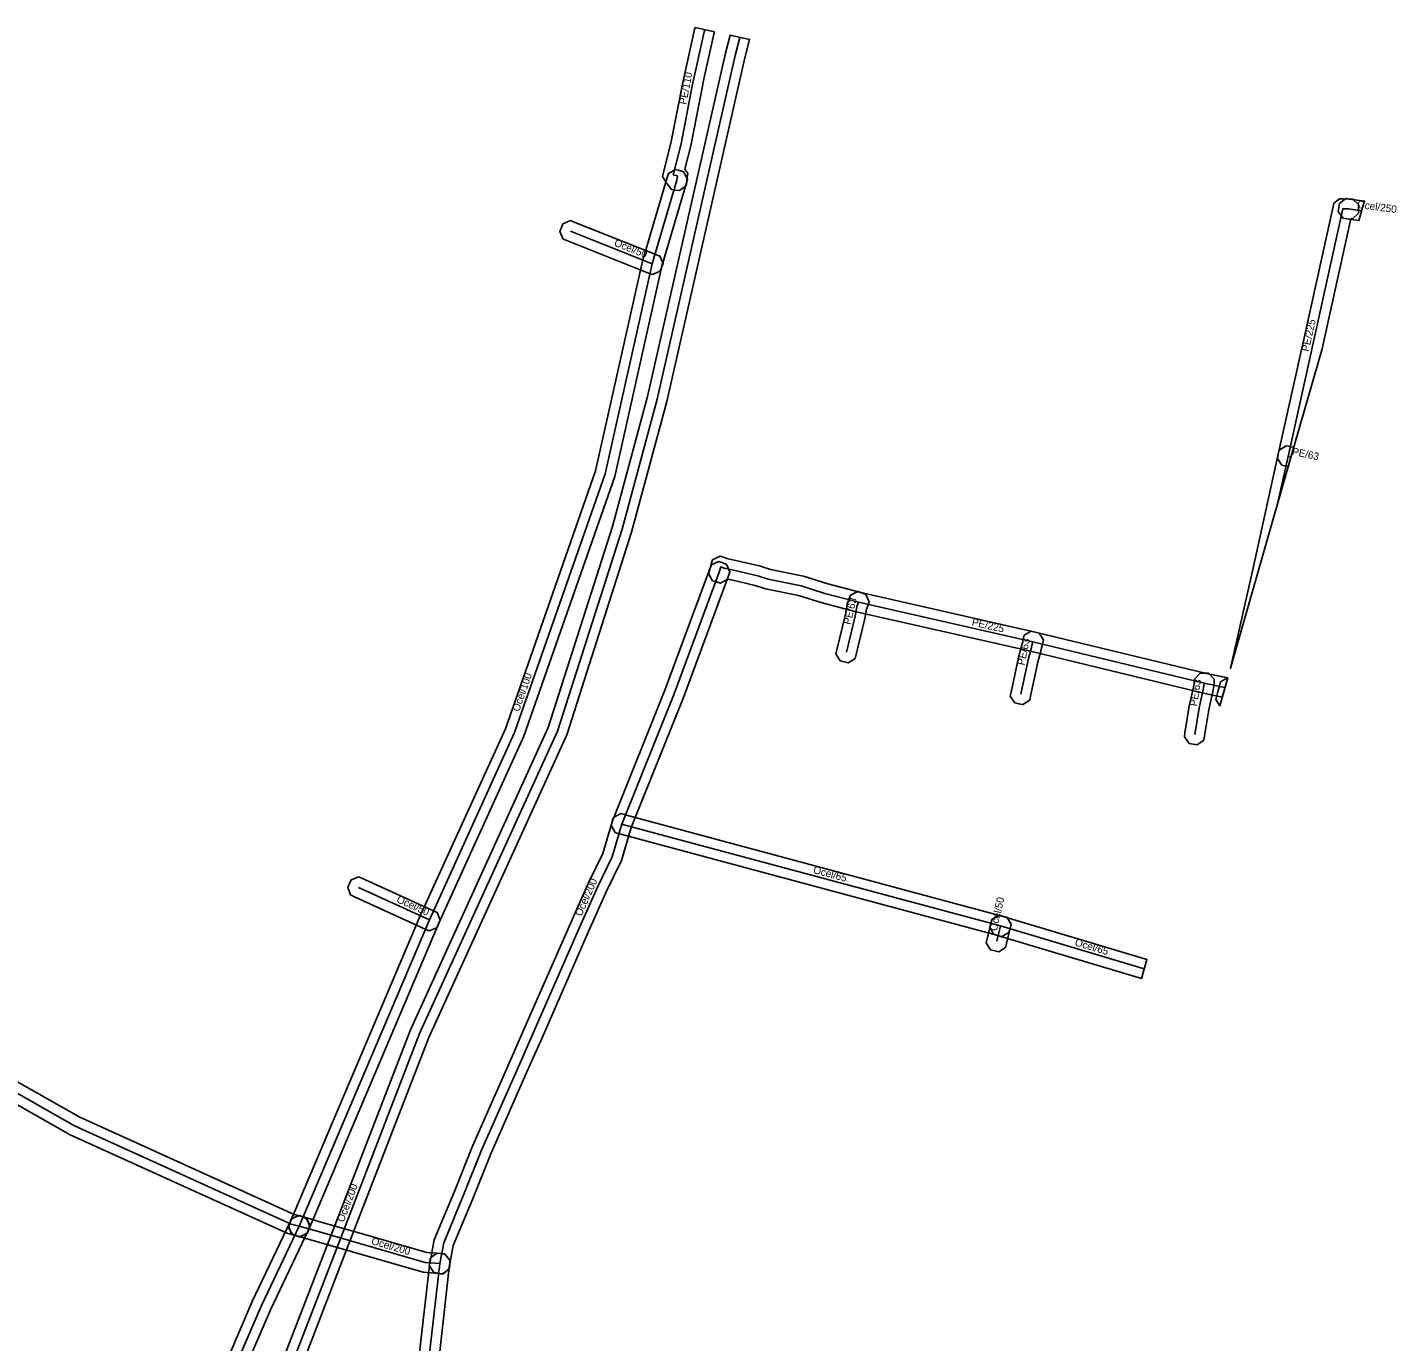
# Model space of a CAD drawing. Extents: x -702919 to -702657, y -1012371 to -1012107.
# Drawn here: x -702794.8 to -702657.1, y -1012238.8 to -1012106.7 of the extents above; entities that cross this region are included whole.
import ezdxf

# ---------------------------------------------------------------- set-up
doc = ezdxf.new("R2010")
doc.units = 0
for name, color, linetype in [('1', 7, 'Continuous'), ('14', 7, 'Continuous'), ('20', 7, 'Continuous'), ('24', 7, 'Continuous'), ('30', 7, 'Continuous')]:
    doc.layers.add(name, color=color, linetype=linetype)

msp = doc.modelspace()

# ---------------------------------------------------------------- linework, layer by layer
at = {"layer": '1'}
for points in [[(-702771.48, -1012246.91), (-702764.83, -1012229.68), (-702756.24, -1012207.49), (-702742.38, -1012177.11), (-702735.92, -1012156.89), (-702732.39, -1012143.83), (-702724.56, -1012109.28), (-702724.09, -1012107.49), (-702722.13, -1012107.92), (-702722.61, -1012109.75), (-702730.45, -1012144.31), (-702734, -1012157.46), (-702740.51, -1012177.83), (-702754.4, -1012208.27), (-702762.96, -1012230.4), (-702769.42, -1012247.1)], [(-702803.11, -1012208.58), (-702789.55, -1012216.25), (-702767.92, -1012226.08), (-702767.17, -1012226.27), (-702766.77, -1012226.37), (-702766.35, -1012227.09), (-702766.45, -1012227.49), (-702766.55, -1012227.89), (-702767.27, -1012228.31), (-702767.67, -1012228.21), (-702768.58, -1012227.98), (-702790.46, -1012218.04), (-702804.11, -1012210.31)], [(-702774.49, -1012240.3), (-702772.15, -1012234.82), (-702768.32, -1012226.81), (-702768.14, -1012226.44), (-702767.36, -1012226.16), (-702766.99, -1012226.34), (-702766.61, -1012226.52), (-702766.34, -1012227.3), (-702766.52, -1012227.67), (-702770.32, -1012235.65), (-702772.41, -1012240.53)]]:
    msp.add_lwpolyline(points, dxfattribs=at)
for points in [[(-702727.62, -1012106.7), (-702725.67, -1012107.14), (-702725.73, -1012107.38), (-702726.83, -1012112.35), (-702726.85, -1012112.45), (-702728.05, -1012118.63), (-702728.64, -1012120.96), (-702728.35, -1012121.39), (-702728.4, -1012121.78), (-702728.46, -1012122.21), (-702728.52, -1012122.62), (-702729.18, -1012123.12), (-702729.59, -1012123.06), (-702730, -1012123), (-702730.44, -1012122.42), (-702730.45, -1012122.42), (-702730.67, -1012122.06), (-702730.89, -1012121.7), (-702730.79, -1012121.3), (-702730.01, -1012118.19), (-702728.81, -1012112.07), (-702728.79, -1012111.95), (-702727.67, -1012106.92)], [(-702768.5, -1012227.23), (-702768.34, -1012226.85), (-702755.25, -1012196.04), (-702746.69, -1012177.22), (-702737.63, -1012151.3), (-702732.89, -1012130.22), (-702730.41, -1012121.79), (-702730.29, -1012121.39), (-702729.57, -1012120.99), (-702729.17, -1012121.11), (-702728.77, -1012121.23), (-702728.37, -1012121.95), (-702728.49, -1012122.35), (-702730.95, -1012130.72), (-702735.7, -1012151.85), (-702744.83, -1012177.96), (-702753.42, -1012196.85), (-702766.5, -1012227.63), (-702766.66, -1012228.01), (-702767.43, -1012228.32), (-702767.81, -1012228.16), (-702768.19, -1012228)], [(-702667.73, -1012150.04), (-702673.78, -1012171.14), (-702671.52, -1012161.2), (-702668.97, -1012149.62), (-702666.31, -1012137.63), (-702663.47, -1012124.73), (-702663.39, -1012124.39), (-702662.83, -1012123.94), (-702662.47, -1012123.95), (-702661.88, -1012123.96), (-702661.47, -1012123.97), (-702660.89, -1012124.56), (-702660.9, -1012124.98), (-702660.91, -1012125.39), (-702661.5, -1012125.97), (-702661.69, -1012125.96), (-702664.35, -1012138.07), (-702664.57, -1012139.04)], [(-702660.33, -1012124.26), (-702660.86, -1012126.11), (-702662.04, -1012125.95), (-702662.45, -1012125.9), (-702662.95, -1012125.23), (-702662.89, -1012124.83), (-702662.83, -1012124.42), (-702662.18, -1012123.91), (-702661.77, -1012123.97), (-702660.3, -1012124.17), (-702660.32, -1012124.23)], [(-702731.9, -1012131.55), (-702732.29, -1012131.4), (-702740.5, -1012128.14), (-702740.88, -1012127.99), (-702741.21, -1012127.23), (-702741.06, -1012126.84), (-702740.91, -1012126.46), (-702740.15, -1012126.13), (-702739.76, -1012126.28), (-702731.55, -1012129.54), (-702731.16, -1012129.7), (-702730.83, -1012130.46), (-702730.99, -1012130.84), (-702731.14, -1012131.23)], [(-702667.73, -1012150.04), (-702667.96, -1012150.87), (-702668.2, -1012150.82), (-702668.6, -1012150.73), (-702669.06, -1012150.04), (-702668.97, -1012149.63), (-702668.88, -1012149.22), (-702668.19, -1012148.78), (-702667.78, -1012148.86), (-702667.5, -1012148.92), (-702667.41, -1012148.94)], [(-702674.06, -1012172.11), (-702674.62, -1012174.04), (-702676.63, -1012173.62), (-702693.88, -1012169.44), (-702711.43, -1012165.48), (-702714.84, -1012164.57), (-702717.21, -1012163.83), (-702720.52, -1012163.14), (-702721.57, -1012162.81), (-702723.97, -1012162.26), (-702724.37, -1012162.18), (-702725.06, -1012162.57), (-702725.46, -1012162.45), (-702725.86, -1012162.34), (-702726.27, -1012161.62), (-702726.15, -1012161.22), (-702726, -1012160.68), (-702725.88, -1012160.25), (-702725.48, -1012160.05), (-702725.08, -1012159.86), (-702724.67, -1012160.02), (-702724.41, -1012160.12), (-702724.17, -1012160.17), (-702723.53, -1012160.31), (-702721.05, -1012160.87), (-702720.02, -1012161.2), (-702716.71, -1012161.89), (-702714.28, -1012162.65), (-702710.95, -1012163.54), (-702693.42, -1012167.5), (-702676.19, -1012171.66)], [(-702754.35, -1012231.21), (-702754.27, -1012230.8), (-702753.85, -1012228.61), (-702751.85, -1012223.81), (-702750.01, -1012219.2), (-702746.32, -1012210.86), (-702744.83, -1012207.48), (-702740.29, -1012197.1), (-702738.33, -1012192.73), (-702736.9, -1012189.76), (-702735.93, -1012186.49), (-702730.65, -1012173.35), (-702726.13, -1012161.14), (-702725.98, -1012160.75), (-702725.23, -1012160.41), (-702724.84, -1012160.55), (-702724.45, -1012160.7), (-702724.11, -1012161.45), (-702724.25, -1012161.84), (-702728.79, -1012174.07), (-702734.04, -1012187.15), (-702735.02, -1012190.48), (-702736.51, -1012193.57), (-702738.46, -1012197.91), (-702743, -1012208.29), (-702744.49, -1012211.67), (-702748.17, -1012219.98), (-702750, -1012224.56), (-702751.93, -1012229.19), (-702752.31, -1012231.18), (-702752.39, -1012231.59), (-702753.07, -1012232.05), (-702753.48, -1012231.97), (-702753.89, -1012231.89)], [(-702710.25, -1012164.85), (-702710.37, -1012165.19), (-702710.54, -1012166.13), (-702711.43, -1012169.76), (-702711.53, -1012170.16), (-702712.23, -1012170.59), (-702712.64, -1012170.49), (-702713.04, -1012170.39), (-702713.47, -1012169.69), (-702713.37, -1012169.28), (-702712.5, -1012165.71), (-702712.33, -1012164.78), (-702712.31, -1012164.67), (-702712.13, -1012164.17), (-702711.99, -1012163.78), (-702711.24, -1012163.43), (-702710.85, -1012163.57), (-702710.46, -1012163.71), (-702710.11, -1012164.46)], [(-702692.58, -1012168.3), (-702692.68, -1012168.71), (-702692.77, -1012169.09), (-702692.86, -1012169.44), (-702693.16, -1012170.52), (-702693.88, -1012173.95), (-702693.97, -1012174.35), (-702694.66, -1012174.8), (-702695.07, -1012174.72), (-702695.47, -1012174.63), (-702695.92, -1012173.94), (-702695.84, -1012173.53), (-702695.1, -1012170.06), (-702694.8, -1012168.92), (-702694.71, -1012168.59), (-702694.62, -1012168.23), (-702694.52, -1012167.83), (-702693.82, -1012167.4), (-702693.41, -1012167.5), (-702693.01, -1012167.6)], [(-702677.51, -1012173.06), (-702677.41, -1012172.59), (-702677.41, -1012172.23), (-702676.82, -1012171.64), (-702676.41, -1012171.64), (-702676, -1012171.64), (-702675.41, -1012172.23), (-702675.41, -1012172.64), (-702675.41, -1012172.81), (-702675.56, -1012173.48), (-702675.96, -1012175.32), (-702676.38, -1012177.95), (-702676.45, -1012178.36), (-702677.12, -1012178.84), (-702677.53, -1012178.78), (-702677.94, -1012178.71), (-702678.42, -1012178.04), (-702678.36, -1012177.63), (-702677.92, -1012174.94)], [(-702674.09, -1012172.09), (-702674.06, -1012172.1), (-702674.86, -1012174.91), (-702675.02, -1012174.66), (-702675.24, -1012174.3), (-702675.14, -1012173.89), (-702675.07, -1012173.6), (-702674.9, -1012172.92), (-702674.8, -1012172.52)], [(-702696.77, -1012198.12), (-702697.17, -1012198.02), (-702735.07, -1012187.84), (-702735.27, -1012187.78), (-702735.67, -1012187.66), (-702736.06, -1012186.93), (-702735.94, -1012186.53), (-702735.83, -1012186.14), (-702735.1, -1012185.74), (-702734.7, -1012185.86), (-702734.52, -1012185.92), (-702696.65, -1012196.09), (-702696.25, -1012196.19), (-702695.84, -1012196.91), (-702695.95, -1012197.31), (-702696.06, -1012197.71)], [(-702761.43, -1012192.12), (-702761.05, -1012192.29), (-702753.92, -1012195.54), (-702753.55, -1012195.71), (-702753.26, -1012196.48), (-702753.43, -1012196.86), (-702753.6, -1012197.24), (-702754.37, -1012197.53), (-702754.75, -1012197.36), (-702761.88, -1012194.11), (-702762.26, -1012193.94), (-702762.55, -1012193.17), (-702762.38, -1012192.79), (-702762.2, -1012192.41)], [(-702695.84, -1012196.87), (-702695.94, -1012197.28), (-702696.29, -1012198.81), (-702696.39, -1012199.21), (-702697.09, -1012199.65), (-702697.49, -1012199.56), (-702697.9, -1012199.47), (-702698.34, -1012198.76), (-702698.24, -1012198.36), (-702697.89, -1012196.83), (-702697.79, -1012196.42), (-702697.09, -1012195.98), (-702696.69, -1012196.08), (-702696.28, -1012196.17)], [(-702696.63, -1012196.09), (-702682.19, -1012200.42), (-702682.74, -1012202.34), (-702697.2, -1012198.01), (-702697.6, -1012197.89), (-702697.99, -1012197.16), (-702697.87, -1012196.77), (-702697.75, -1012196.37), (-702697.02, -1012195.97)], [(-702752.95, -1012232.02), (-702753.36, -1012231.99), (-702754.95, -1012231.87), (-702761.51, -1012229.98), (-702765.67, -1012228.79), (-702767.7, -1012228.2), (-702768.09, -1012228.09), (-702768.49, -1012227.36), (-702768.38, -1012226.96), (-702768.27, -1012226.57), (-702767.54, -1012226.17), (-702767.14, -1012226.28), (-702765.11, -1012226.86), (-702760.96, -1012228.06), (-702754.59, -1012229.89), (-702753.22, -1012229.99), (-702752.8, -1012230.02), (-702752.26, -1012230.65), (-702752.29, -1012231.06), (-702752.32, -1012231.48)], [(-702752.25, -1012230.69), (-702752.3, -1012231.1), (-702753.29, -1012239.84), (-702754.33, -1012250.62), (-702755.17, -1012261.94), (-702752.51, -1012263.68), (-702752.16, -1012263.91), (-702751.99, -1012264.72), (-702752.22, -1012265.06), (-702752.45, -1012265.41), (-702753.26, -1012265.58), (-702753.6, -1012265.35), (-702756.76, -1012263.29), (-702756.99, -1012263.14), (-702757.23, -1012262.65), (-702757.21, -1012262.38), (-702756.33, -1012250.45), (-702755.28, -1012239.63), (-702754.28, -1012230.88), (-702754.24, -1012230.46), (-702753.59, -1012229.95), (-702753.18, -1012230), (-702752.77, -1012230.04)]]:
    msp.add_lwpolyline(points, close=True, dxfattribs=at)
at = {"layer": '14'}
for points in [[(-702726.64, -1012106.92), (-702726.7, -1012107.15), (-702727.81, -1012112.15), (-702727.83, -1012112.26), (-702729.03, -1012118.41), (-702729.82, -1012121.54), (-702729.39, -1012121.64), (-702729.45, -1012122.07)], [(-702767.42, -1012227.24), (-702754.34, -1012196.45), (-702745.76, -1012177.59), (-702736.67, -1012151.58), (-702731.92, -1012130.47), (-702729.45, -1012122.07)], [(-702661.9, -1012124.96), (-702662.49, -1012124.95), (-702665.33, -1012137.85), (-702667.99, -1012149.84), (-702669.04, -1012154.62)], [(-702660.58, -1012125.14), (-702661.9, -1012124.96)], [(-702731.92, -1012130.47), (-702740.13, -1012127.21)], [(-702908.14, -1012150.23), (-702887.78, -1012161.76), (-702873.19, -1012169.73), (-702866.02, -1012173.64), (-702864.83, -1012174.26), (-702860.99, -1012176.26), (-702853.62, -1012180.19), (-702845.63, -1012184.76), (-702837.42, -1012189.43), (-702803.61, -1012209.45), (-702790.01, -1012217.15), (-702768.25, -1012227.03), (-702767.42, -1012227.24)], [(-702667.99, -1012149.84), (-702667.71, -1012149.9), (-702667.69, -1012149.9)], [(-702753.29, -1012230.99), (-702752.89, -1012228.9), (-702750.93, -1012224.19), (-702749.09, -1012219.59), (-702745.41, -1012211.27), (-702743.92, -1012207.89), (-702739.38, -1012197.5), (-702737.42, -1012193.15), (-702735.96, -1012190.12), (-702734.98, -1012186.82), (-702729.72, -1012173.71), (-702725.19, -1012161.49)], [(-702674.34, -1012173.07), (-702676.41, -1012172.64), (-702693.65, -1012168.47), (-702711.19, -1012164.51), (-702714.56, -1012163.61), (-702716.96, -1012162.86), (-702720.27, -1012162.17), (-702721.31, -1012161.84), (-702723.75, -1012161.29), (-702724.37, -1012161.15), (-702724.69, -1012161.09), (-702725.04, -1012160.95), (-702725.19, -1012161.49)], [(-702711.19, -1012164.51), (-702711.34, -1012164.93), (-702711.34, -1012164.96), (-702711.52, -1012165.92), (-702712.4, -1012169.52)], [(-702693.65, -1012168.47), (-702693.74, -1012168.84), (-702693.83, -1012169.18), (-702694.13, -1012170.29), (-702694.86, -1012173.74)], [(-702676.41, -1012172.64), (-702676.41, -1012172.7), (-702676.53, -1012173.27), (-702676.94, -1012175.13), (-702677.37, -1012177.79)], [(-702696.91, -1012197.05), (-702734.79, -1012186.88), (-702734.98, -1012186.82)], [(-702761.47, -1012193.2), (-702754.34, -1012196.45)], [(-702696.91, -1012197.05), (-702697.27, -1012198.59)], [(-702682.46, -1012201.38), (-702696.91, -1012197.05)], [(-702769.35, -1012267.7), (-702770.81, -1012257.21), (-702770.85, -1012256.76), (-702771.27, -1012253.33), (-702772.12, -1012247.54), (-702773.45, -1012240.41), (-702771.23, -1012235.23), (-702767.42, -1012227.24)], [(-702753.29, -1012230.99), (-702754.77, -1012230.88), (-702761.23, -1012229.02), (-702765.39, -1012227.82), (-702767.42, -1012227.24)], [(-702753.29, -1012230.99), (-702754.29, -1012239.73), (-702755.33, -1012250.53), (-702756.21, -1012262.45), (-702753.06, -1012264.52)]]:
    msp.add_lwpolyline(points, dxfattribs=at)
at = {"layer": '24'}
msp.add_lwpolyline([(-702792.14, -1012341.37), (-702788.14, -1012324.25), (-702787, -1012319.38), (-702764.71, -1012298.48), (-702767.29, -1012267.3), (-702767.75, -1012261.76), (-702769.06, -1012254.65), (-702770.45, -1012247), (-702763.89, -1012230.04), (-702755.32, -1012207.88), (-702741.45, -1012177.47), (-702734.96, -1012157.17), (-702731.42, -1012144.07), (-702723.58, -1012109.52), (-702723.11, -1012107.71)], dxfattribs=at)

# ---------------------------------------------------------------- texts
at = {"layer": '20'}
for s, rotation, p in [('PE/110', 78.9698, (-702728.51, -1012114.51)), ('Ocel/250', 352.2467, (-702661.09, -1012124.84)), ('Ocel/50', 338.3503, (-702735.82, -1012128.64)), ('PE/225', 77.4914, (-702665.91, -1012139.35)), ('PE/63', 347.8777, (-702667.64, -1012149.67)), ('PE/63', 76.2637, (-702711.99, -1012166.81)), ('PE/225', 347.2776, (-702699.84, -1012166.83)), ('PE/63', 78.0528, (-702694.5, -1012170.89)), ('Ocel/100', 70.7399, (-702745.32, -1012175.56)), ('PE/63', 80.8173, (-702677.15, -1012175)), ('Ocel/65', 344.965, (-702715.8, -1012191.73)), ('Ocel/200', 65.7816, (-702739.06, -1012196.15)), ('Ocel/50', 335.5355, (-702757.7, -1012194.63)), ('Ocel/50', 76.9617, (-702697.29, -1012197.62)), ('Ocel/65', 343.339, (-702689.49, -1012199.01)), ('Ocel/200', 343.9446, (-702760.23, -1012229.05))]:
    msp.add_text(s, height=0.75, rotation=rotation, dxfattribs=at).set_placement(p)
at = {"layer": '30'}
msp.add_text('Ocel/200', height=0.75, rotation=68.8395, dxfattribs=at).set_placement((-702762.96, -1012226.9))

doc.saveas('drawing.dxf')
